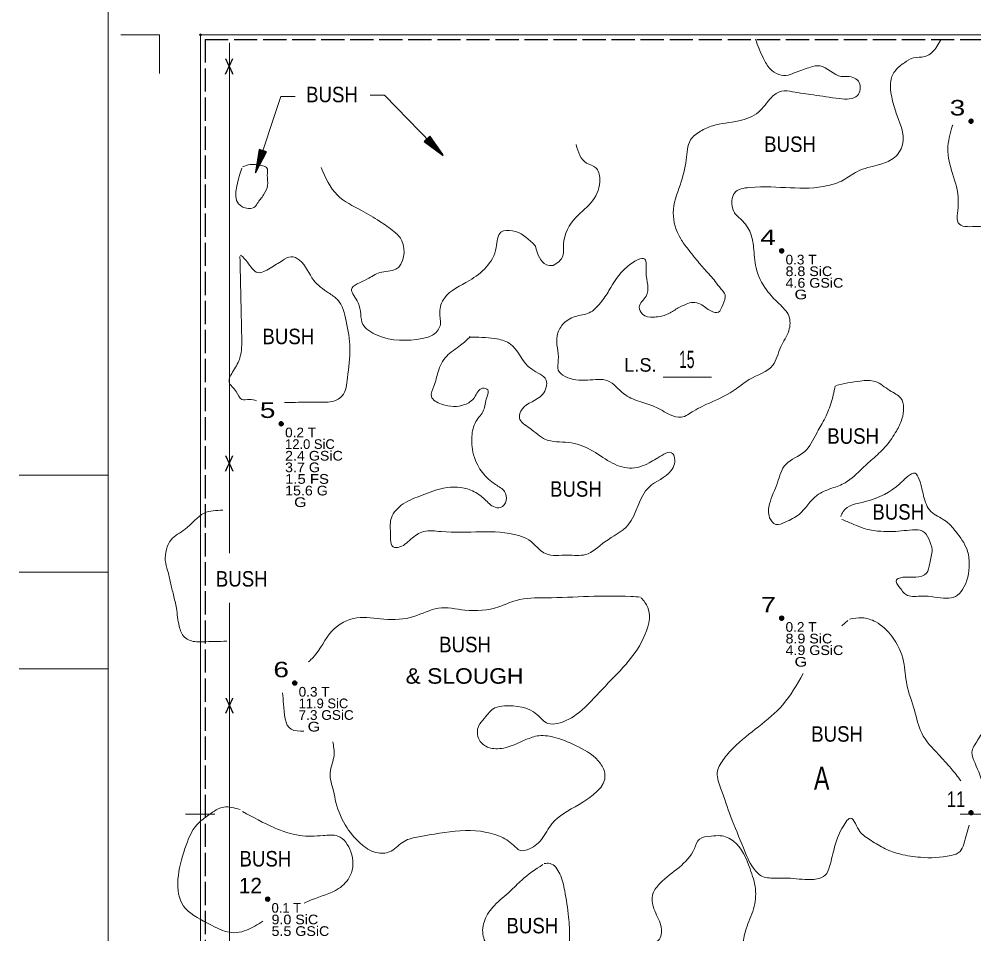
# Model space of a CAD drawing. Extents: x -496 to 480, y -452 to 700.
# Drawn here: x -496.1 to -2.8, y -61.9 to 410.5 of the extents above; entities that cross this region are included whole.
import ezdxf
from ezdxf.enums import TextEntityAlignment as Align

# ---------------------------------------------------------------- set-up
doc = ezdxf.new("R2010")
doc.units = 0
doc.header["$LTSCALE"] = 2
doc.header["$PDMODE"] = 32
doc.header["$PDSIZE"] = 1
doc.linetypes.add('LONG_DASHED', pattern=[7.5, 6, -1.5])
doc.layers.add('3', color=7, linetype='Continuous', lineweight=13)

msp = doc.modelspace()

# ---------------------------------------------------------------- linework, layer by layer
at = {"layer": '3'}
for p, q in [((-423.537, 402.339), (-443.537, 402.339)), ((-423.537, 402.339), (-423.537, 382.339)), ((-402.391, 402.339), (-402.391, -402.333)), ((-382.391, 402.339), (-402.391, 402.339)), ((-387.448, 398.168), (-387.448, 134.718)), ((-230.688, 294.819), (-229.391, 293.153)), ((-220.248, 283.152), (-217.731, 284.727)), ((-163.382, 225.602), (-138.382, 225.602)), ((-450.017, 174.973), (-496.057, 174.973)), ((-450.017, 124.973), (-496.057, 124.973)), ((-387.448, 109.099), (-387.448, -402.333)), ((-71.129, 97.14), (-68.036, 99.92)), ((-450.017, 74.973), (-496.057, 74.973)), ((-395.017, -0.027), (-410.017, -0.027)), ((-10.017, -0.027), (9.983, -0.027))]:
    msp.add_line(p, q, dxfattribs=at)
at = {"layer": '3', "linetype": 'LONG_DASHED', "lineweight": 25}
for q in [(292.281, 400), (-400, -400)]:
    msp.add_line((-400, 400), q, dxfattribs=at)
at = {"layer": '3'}
for points in [[(449.983, -450.027), (449.983, 399.973), (449.983, 699.973), (-450.017, 699.973), (-450.017, 49.973), (-450.017, -450.027)], [(402.281, -402.333), (402.281, 402.339), (-402.391, 402.339)], [(-353.522, 370.559), (-360.926, 370.559), (-373.884, 331.114)], [(-314.648, 371.175), (-307.243, 371.175), (-277.008, 340.05)]]:
    msp.add_lwpolyline(points, dxfattribs=at)
at = {"layer": '3', "lineweight": 25}
for points in [[(-277.008, 340.05), (-283.935, 350.051), (-286.804, 347.264)], [(-373.884, 331.114), (-368.239, 341.89), (-372.039, 343.138)]]:
    msp.add_lwpolyline(points, close=True, dxfattribs=at)
for points in [[(-283.951, 349.899), (-277.407, 340.463), (-286.573, 347.262), (-284.045, 349.746), (-277.92, 340.991), (-286.314, 347.242), (-284.034, 349.518), (-278.463, 341.549), (-286.023, 347.254), (-284.098, 349.275), (-279.064, 342.198), (-285.717, 347.218), (-284.103, 348.967), (-279.787, 342.975), (-285.395, 347.259), (-284.139, 348.632), (-280.569, 343.81), (-284.967, 347.285), (-284.127, 348.281), (-281.397, 344.756), (-284.541, 347.218), (-284.087, 347.868), (-282.452, 345.812), (-284.007, 347.194)], [(-368.382, 341.834), (-373.704, 331.658), (-371.934, 342.932), (-368.561, 341.846), (-373.474, 332.358), (-371.832, 342.694), (-368.757, 341.731), (-373.231, 333.098), (-371.685, 342.441), (-369.002, 341.674), (-372.936, 333.932), (-371.575, 342.154), (-369.277, 341.536), (-372.582, 334.932), (-371.389, 341.888), (-369.591, 341.412), (-372.205, 336.013), (-371.169, 341.521), (-369.896, 341.239), (-371.752, 337.185), (-371.03, 341.112), (-370.244, 341.012), (-371.306, 338.609), (-370.804, 340.628)]]:
    msp.add_lwpolyline(points, dxfattribs=at)
at = {"layer": '3', "lineweight": 35}
for centre in [(-4.317, 357.711), (-102.135, 290.769), (-360.654, 201.513), (-102.135, 101.1), (-353.667, 67.629), (-4.317, 0.687), (-367.641, -43.941)]:
    msp.add_circle(centre, 1, dxfattribs=at)
at = {"layer": '3'}
for points in [[(-115.696, 400.023), (-111.547, 390.14), (-108.036, 384.72), (-103.567, 381.851), (-98.78, 381.532), (-94.63, 383.126), (-90.8, 384.401), (-87.289, 385.676), (-82.501, 386.314), (-71.33, 380.894), (-68.138, 380.894), (-62.074, 377.706), (-63.032, 371.011), (-72.288, 369.417), (-85.693, 371.33), (-96.545, 372.924), (-102.291, 373.243), (-107.397, 370.055), (-114.1, 362.403), (-124.314, 357.94), (-137.719, 355.389), (-144.103, 352.52), (-149.21, 348.057), (-151.444, 337.855), (-154.636, 324.784), (-158.147, 310.437), (-154.317, 297.047), (-150.486, 291.628), (-146.656, 286.846), (-141.869, 281.107), (-136.443, 275.05), (-133.57, 271.224), (-131.336, 268.036), (-132.612, 262.935), (-134.847, 259.109), (-138.677, 259.747), (-144.103, 263.254), (-147.933, 264.21), (-151.444, 263.254), (-155.593, 261.341), (-160.381, 258.472), (-165.488, 256.878), (-168.36, 256.559), (-174.106, 258.153), (-175.702, 261.66), (-172.191, 267.398), (-172.191, 279.832), (-172.829, 286.527), (-181.766, 282.701), (-191.341, 270.268), (-195.81, 263.891), (-201.555, 258.79), (-208.896, 256.878), (-215.28, 252.733), (-218.152, 246.995), (-217.514, 234.242), (-217.514, 229.141), (-214.003, 225.953), (-202.513, 224.04), (-191.98, 223.721), (-183.681, 217.027), (-176.021, 213.201), (-167.722, 210.332), (-159.743, 206.187), (-153.997, 204.912), (-147.614, 208.1), (-138.677, 212.563), (-125.591, 219.577), (-118.888, 224.359), (-106.759, 231.692), (-102.61, 241.256), (-98.46, 249.545), (-98.46, 257.196), (-103.567, 263.573), (-109.951, 270.586), (-115.377, 282.063), (-116.654, 292.584), (-118.249, 299.917), (-123.037, 306.931), (-126.867, 311.075), (-127.825, 316.814), (-126.548, 320.639), (-118.569, 323.509), (-78.352, 324.465), (-70.373, 327.334), (-63.032, 331.798), (-51.86, 335.305), (-44.519, 338.493), (-39.732, 345.506), (-43.562, 363.679), (-45.796, 372.605)], [(-45.796, 372.605), (-45.796, 378.663), (-43.243, 384.082), (-38.774, 387.908), (-33.986, 390.458), (-28.241, 391.096), (-24.411, 393.328), (-19.942, 399.704)], [(301.264, 311.258), (296.565, 300.963), (289.413, 288.462), (287.029, 281.319), (281.07, 278.343), (257.232, 280.129), (241.737, 276.557), (236.97, 271.795), (230.414, 264.057), (224.455, 259.294), (214.919, 256.913), (204.192, 256.318), (197.041, 259.89), (182.142, 268.223), (175.587, 274.771), (171.415, 281.319), (167.243, 284.891), (157.708, 283.105), (149.365, 281.319), (133.87, 274.771), (125.527, 265.842), (116.588, 259.294), (109.436, 257.509), (99.305, 260.485), (93.942, 263.461), (84.406, 265.842), (74.871, 266.438), (70.104, 261.676), (64.74, 246.794), (64.144, 227.15), (62.356, 223.579), (55.205, 225.365), (53.417, 229.531), (51.629, 234.889), (45.074, 240.841), (26.599, 245.604), (21.832, 253.937), (18.852, 268.819), (14.68, 283.7), (14.084, 292.034), (14.084, 302.153), (14.68, 306.32), (9.913, 304.534), (-0.814, 303.344), (-10.35, 304.534), (-10.946, 314.654), (-16.309, 342.036), (-14.521, 353.346), (-13.809, 355.669)], [(-217.731, 284.727), (-215.511, 287.402), (-214.829, 294.212), (-208.352, 308.172), (-199.83, 316.684), (-196.081, 327.92), (-198.126, 333.708), (-202.898, 336.091), (-208.352, 345.625)], [(-380.709, 334.153), (-376.708, 335.369), (-370.969, 334.848), (-368.186, 333.805), (-367.838, 329.81), (-367.664, 324.598), (-369.751, 319.733), (-373.056, 315.216), (-374.795, 313.132), (-378.621, 312.784), (-381.056, 313.653), (-381.056, 333.458)], [(-340.009, 333.805), (-331.661, 319.56), (-319.138, 311.568), (-309.746, 306.009), (-302.441, 300.797), (-298.266, 295.933), (-301.397, 281.34), (-309.746, 279.603), (-316.355, 276.128), (-324.356, 270.916), (-320.877, 263.967), (-318.442, 252.849), (-311.137, 247.289), (-287.831, 245.552), (-281.917, 247.637), (-278.438, 252.849), (-278.786, 259.103), (-276.351, 266.399), (-263.481, 275.433), (-254.784, 282.382), (-249.566, 292.458), (-247.131, 300.45), (-241.218, 301.145), (-230.688, 294.819)], [(-229.391, 293.153), (-223.692, 283.657), (-220.248, 283.152)], [(-373.412, 213.433), (-377.066, 214.124), (-381.084, 214.124), (-383.88, 218.138), (-387.55, 223.025), (-385.278, 228.959), (-381.958, 235.591), (-381.084, 246.412), (-381.958, 287.951)], [(-381.609, 288.649), (-378.114, 284.983), (-372.872, 279.573), (-366.407, 281.842), (-359.942, 285.856), (-355.573, 287.776), (-351.205, 286.031), (-343.866, 275.559), (-336.178, 269.101), (-331.635, 265.611), (-327.092, 254.441), (-325.17, 240.478), (-326.393, 225.294), (-329.189, 215.869), (-333.557, 213.251), (-341.07, 212.728), (-353.302, 212.553), (-358.89, 212.514)], [(-263.515, 246.274), (-250.287, 245.481), (-242.879, 243.103), (-231.238, 229.625), (-223.83, 224.076), (-225.682, 216.677), (-236.265, 209.013), (-237.588, 204.521), (-232.296, 199.235), (-224.095, 193.422), (-212.189, 191.836), (-200.813, 188.136), (-190.759, 181.794), (-180.706, 178.623), (-170.652, 181.266), (-162.98, 185.758), (-159.011, 186.551), (-157.689, 184.701), (-159.276, 177.302), (-170.652, 168.845), (-181.5, 149.29), (-193.405, 140.569), (-203.459, 133.963), (-212.718, 133.699), (-224.095, 134.491), (-227.27, 136.606), (-232.826, 141.627), (-237.852, 143.741), (-278.067, 145.855), (-287.062, 145.855), (-293.676, 141.891), (-300.29, 137.663), (-302.142, 137.663), (-304.259, 145.326), (-303.73, 152.99), (-297.644, 160.125), (-287.856, 164.617), (-276.744, 168.317), (-262.722, 167.26), (-256.107, 163.032), (-251.081, 158.803), (-247.377, 158.275), (-244.467, 161.975), (-245.26, 166.467), (-250.022, 170.167), (-260.87, 184.172), (-262.193, 195.007), (-260.076, 202.671), (-256.107, 208.484), (-254.52, 215.091), (-253.991, 219.055), (-256.637, 219.848), (-260.87, 215.091), (-265.896, 211.391), (-277.802, 211.656), (-283.093, 215.619), (-281.77, 220.905), (-279.654, 228.304), (-275.156, 236.496), (-268.013, 242.046), (-262.986, 246.538)], [(-74.176, 221.296), (-61.538, 223.591), (-53.784, 223.304), (-46.316, 218.714), (-40.572, 214.698), (-39.998, 204.083), (-42.87, 197.772), (-48.04, 190.313), (-54.358, 184.002), (-60.39, 178.551), (-69.293, 171.093), (-76.186, 168.224), (-83.941, 164.494), (-93.132, 154.74), (-100.312, 150.724), (-105.194, 149.577), (-108.354, 153.019), (-108.354, 160.191), (-104.333, 171.093), (-100.025, 180.559), (-90.259, 187.158), (-84.228, 196.338), (-80.207, 203.51), (-76.761, 211.829), (-74.463, 221.009)], [(-71.591, 153.593), (-70.442, 156.175), (-58.954, 161.339), (-41.146, 170.519), (-37.126, 174.248), (-33.105, 175.969), (-31.669, 173.961), (-28.796, 164.207), (-25.063, 156.175), (-17.882, 151.585), (-12.138, 145.847), (-6.394, 136.38), (-5.245, 129.208), (-8.692, 116.012), (-12.425, 112.283), (-17.021, 111.422), (-29.658, 112.569), (-37.126, 112.856), (-41.146, 116.873), (-42.87, 120.889), (-40.572, 122.036), (-32.817, 122.323), (-27.36, 124.331), (-25.637, 129.495), (-24.488, 136.38), (-26.212, 142.118), (-29.371, 146.134), (-34.541, 146.708), (-46.029, 145.847), (-52.635, 146.134), (-56.656, 146.708), (-65.559, 149.864), (-71.016, 152.159)], [(-390.859, 156.886), (-400.449, 155.389), (-410.339, 147.007), (-417.532, 141.619), (-419.93, 136.53), (-420.529, 130.842), (-419.331, 125.753), (-417.832, 119.466), (-416.333, 113.18), (-414.835, 106.294), (-413.336, 97.014), (-410.639, 91.327), (-404.345, 88.932), (-401.048, 88.932), (-388.761, 89.231)], [(-346.521, 78.576), (-344.081, 80.888), (-334.371, 94.6), (-321.647, 101.289), (-307.584, 100.62), (-292.182, 101.958), (-279.459, 106.305), (-265.73, 105.302), (-248.319, 106.974), (-239.279, 110.319), (-223.876, 111.657), (-180.013, 112.325), (-174.991, 111.991)], [(-174.656, 111.657), (-171.308, 106.64), (-173.651, 90.586), (-182.692, 77.209), (-194.746, 64.5), (-206.8, 52.46), (-218.184, 46.774), (-222.872, 46.774), (-228.564, 51.456), (-245.306, 55.804), (-250.328, 54.801), (-255.685, 49.45), (-258.699, 45.436), (-258.364, 38.413), (-255.685, 35.403), (-248.989, 33.731), (-240.283, 35.738), (-234.256, 38.413), (-227.559, 40.42), (-218.854, 39.416), (-207.135, 34.734), (-195.75, 26.039), (-193.407, 20.353), (-206.8, 4.969), (-220.863, -5.065), (-226.22, -13.091), (-233.586, -18.443), (-237.27, -18.777), (-240.618, -16.101), (-247.984, -11.419), (-289.503, -11.754), (-297.205, -14.095), (-303.901, -19.111), (-310.598, -20.115), (-318.634, -16.101), (-326.67, -7.071), (-332.362, 5.972), (-333.701, 11.992), (-335.376, 21.356), (-333.367, 30.386), (-334.056, 37.304)], [(-67.104, 100.619), (-60.576, 101.317), (-53.583, 99.222), (-45.19, 91.77), (-39.129, 78.731), (-37.497, 66.856), (-33.534, 53.583), (-29.805, 41.708), (-21.179, 30.764), (-14.652, 23.546), (-9.585, 17.207)], [(-5.288, -5.663), (-8.125, -15.573), (-9.99, -19.298), (-14.652, -21.394), (-30.504, -22.325), (-40.761, -20.695), (-48.687, -17.901), (-55.914, -13.71), (-61.742, -9.053), (-64.073, -4.862), (-66.637, -2.067), (-68.968, -4.163), (-74.796, -16.97), (-77.361, -26.982), (-79.692, -31.639), (-83.888, -33.502), (-96.243, -33.269), (-107.666, -33.036), (-111.163, -32.571), (-116.758, -27.914), (-121.886, -17.435), (-128.414, -1.369), (-133.542, 13.068), (-135.407, 21.217), (-132.377, 27.97), (-127.015, 34.257), (-101.605, 56.378), (-91.037, 72.499)], [(-348.914, 42.778), (-355.466, 43.764), (-359.484, 56.808), (-359.995, 62.519)], [(2.873, 9.804), (2.023, 14.186), (-2.274, 26.258), (-3.885, 31.891), (-0.931, 38.061), (0.949, 41.28)], [(-370.238, -55.37), (-378.569, -59.914), (-383.591, -61.251), (-398.994, -56.235), (-411.048, -47.539), (-410.378, -17.774), (-404.016, -5.399), (-397.989, -0.382), (-390.288, 3.631), (-381.917, 2.293)], [(-380.578, 1.29), (-364.171, -7.071), (-351.113, -11.085), (-339.059, -11.085), (-331.358, -11.419), (-324.661, -19.446), (-324.996, -31.82), (-331.023, -38.509), (-344.751, -44.195), (-348.873, -46.071)], [(-199.95, -106.612), (-199.61, -97.793), (-197.09, -89.738), (-191.294, -83.697), (-185.749, -77.403), (-179.701, -70.607), (-173.149, -67.586), (-168.36, -66.579), (-165.336, -64.566), (-164.58, -57.517), (-168.108, -48.959), (-168.612, -41.155), (-165.084, -35.869), (-147.191, -17.745), (-144.671, -12.962), (-138.623, -11.452), (-133.834, -11.2), (-127.03, -13.969), (-118.461, -28.318), (-115.689, -38.638), (-116.697, -48.959), (-120.477, -59.279), (-122.242, -67.083), (-123.502, -76.9), (-122.242, -87.472), (-117.705, -97.29), (-111.718, -107.854)], [(-224.812, -25.549), (-221.787, -25.549), (-216.747, -30.835), (-214.227, -39.645), (-212.211, -53.238), (-211.707, -63.559), (-212.715, -72.117), (-214.983, -77.152), (-220.275, -78.662), (-226.828, -79.166), (-235.144, -78.159), (-247.241, -72.872), (-252.533, -69.6), (-256.313, -63.055), (-255.557, -54.748), (-250.517, -47.197), (-242.453, -39.897), (-236.404, -34.107), (-225.568, -26.052)]]:
    msp.add_spline(points, degree=3, dxfattribs=at)
at = {"layer": '3', "lineweight": 35}
for points in [[(-4.328, 358.598), (-3.598, 358.194), (-3.446, 357.345), (-4.131, 356.817), (-4.94, 357.048), (-5.227, 357.806), (-4.98, 358.368), (-4.407, 358.536), (-3.733, 358.042), (-3.749, 357.3), (-4.266, 357.042), (-4.789, 357.211), (-5.013, 357.857), (-4.429, 358.323), (-3.991, 357.789), (-4.03, 357.306), (-4.659, 357.441), (-4.513, 358.076), (-4.221, 357.525)], [(-102.146, 291.656), (-101.416, 291.252), (-101.264, 290.403), (-101.949, 289.875), (-102.758, 290.106), (-103.045, 290.864), (-102.798, 291.426), (-102.225, 291.594), (-101.551, 291.1), (-101.567, 290.358), (-102.084, 290.1), (-102.607, 290.269), (-102.831, 290.915), (-102.247, 291.381), (-101.809, 290.847), (-101.848, 290.364), (-102.477, 290.499), (-102.331, 291.134), (-102.039, 290.583)], [(-360.665, 202.4), (-359.935, 201.996), (-359.783, 201.147), (-360.468, 200.619), (-361.277, 200.85), (-361.564, 201.608), (-361.317, 202.17), (-360.744, 202.338), (-360.07, 201.844), (-360.086, 201.102), (-360.603, 200.844), (-361.126, 201.013), (-361.35, 201.659), (-360.766, 202.125), (-360.328, 201.591), (-360.367, 201.108), (-360.996, 201.243), (-360.85, 201.878), (-360.558, 201.327)], [(-102.146, 101.987), (-101.416, 101.583), (-101.264, 100.734), (-101.949, 100.206), (-102.758, 100.437), (-103.045, 101.195), (-102.798, 101.757), (-102.225, 101.925), (-101.551, 101.431), (-101.567, 100.689), (-102.084, 100.431), (-102.607, 100.6), (-102.831, 101.246), (-102.247, 101.712), (-101.809, 101.178), (-101.848, 100.695), (-102.477, 100.83), (-102.331, 101.465), (-102.039, 100.914)], [(-353.678, 68.516), (-352.948, 68.112), (-352.796, 67.263), (-353.481, 66.735), (-354.29, 66.966), (-354.577, 67.724), (-354.33, 68.286), (-353.757, 68.454), (-353.083, 67.96), (-353.099, 67.218), (-353.616, 66.96), (-354.139, 67.129), (-354.363, 67.775), (-353.779, 68.241), (-353.341, 67.707), (-353.38, 67.224), (-354.009, 67.359), (-353.863, 67.994), (-353.571, 67.443)], [(-4.328, 1.574), (-3.598, 1.17), (-3.446, 0.321), (-4.131, -0.207), (-4.94, 0.024), (-5.227, 0.782), (-4.98, 1.344), (-4.407, 1.512), (-3.733, 1.018), (-3.749, 0.276), (-4.266, 0.018), (-4.789, 0.187), (-5.013, 0.833), (-4.429, 1.299), (-3.991, 0.765), (-4.03, 0.282), (-4.659, 0.417), (-4.513, 1.052), (-4.221, 0.501)], [(-367.652, -43.054), (-366.922, -43.458), (-366.77, -44.307), (-367.455, -44.835), (-368.264, -44.604), (-368.551, -43.846), (-368.304, -43.284), (-367.731, -43.116), (-367.057, -43.61), (-367.073, -44.352), (-367.59, -44.61), (-368.113, -44.441), (-368.337, -43.795), (-367.753, -43.329), (-367.315, -43.863), (-367.354, -44.346), (-367.983, -44.211), (-367.837, -43.576), (-367.545, -44.127)]]:
    msp.add_spline(points, degree=3, dxfattribs=at)
at = {"layer": '3'}
msp.add_point((-402.391, 402.339), dxfattribs=at)

# ---------------------------------------------------------------- texts
for s, height, width, p in [('X', 8, 0.7, (-387.565, 381.973)), ('BUSH', 8, 0.9, (-334.44, 367.516)), ('BUSH', 8, 0.9, (-97.819, 341.867)), ('BUSH', 8, 0.9, (-356.987, 242.602)), ('15', 8.89, 0.6, (-151.143, 230.298)), ('BUSH', 8, 0.9, (-65.232, 191.176)), ('X', 8, 0.7, (-387.529, 176.976)), ('BUSH', 8, 0.9, (-208.438, 163.854)), ('BUSH', 8, 0.9, (-41.941, 151.994)), ('BUSH', 8, 0.9, (-381.054, 117.435)), ('BUSH', 8, 0.9, (-265.686, 83.53)), ('& SLOUGH', 8, 1.1, (-265.971, 67.29)), ('X', 8, 0.7, (-387.432, 51.987)), ('BUSH', 8, 0.9, (-73.509, 37.346)), ('A', 12, 0.75, (-81.468, 12.524)), ('BUSH', 8, 0.9, (-368.835, -27.091)), ('BUSH', 8, 0.9, (-230.945, -61.606))]:
    msp.add_text(s, height=height, dxfattribs=dict(at, width=width)).set_placement(p, align=Align.CENTER)
for s, width, p in [('  3', 1.35, (-7.318, 360.711)), ('  4', 1.35, (-105.136, 293.769)), ('  5', 1.35, (-363.655, 204.513)), ('  7', 1.3, (-105.136, 104.1)), ('  6', 1.35, (-356.668, 70.629)), (' 11', 0.8, (-7.318, 3.687))]:
    msp.add_text(s, height=8, dxfattribs=dict(at, width=width)).set_placement(p, align=Align.RIGHT)
for s, width, p in [('0.3 T      ', 1.05, (-100.135, 283.769)), ('8.8 SiC    ', 1.1, (-100.135, 277.769)), ('4.6 GSiC   ', 1.1, (-100.135, 271.769)), ('  G        ', 1.25, (-100.135, 265.769)), ('0.2 T      ', 1.05, (-358.654, 194.513)), ('2.4 GSiC   ', 1.1, (-358.654, 182.513)), ('3.7 G      ', 1.1, (-358.654, 176.513)), ('1.5 FS     ', 1.15, (-358.654, 170.513)), ('15.6 G     ', 1.1, (-358.654, 164.513)), ('  G        ', 1.25, (-358.654, 158.513)), ('0.2 T      ', 1.05, (-100.135, 94.1)), ('8.9 SiC    ', 1.1, (-100.135, 88.1)), ('4.9 GSiC   ', 1.1, (-100.135, 82.1)), ('  G        ', 1.25, (-100.135, 76.1)), ('0.3 T      ', 1.05, (-351.667, 60.629)), ('7.3 GSiC   ', 1.05, (-351.667, 48.629)), ('  G        ', 1.25, (-351.667, 42.629)), ('9.0 SiC    ', 1.1, (-365.641, -56.941)), ('5.5 GSiC   ', 1.1, (-365.641, -62.941))]:
    msp.add_text(s, height=5, dxfattribs=dict(at, width=width)).set_placement(p)
msp.add_text('L.S.', height=7, dxfattribs=at).set_placement((-175.104, 228.395), align=Align.CENTER)
for s, p in [('12.0 SiC   ', (-358.654, 188.513)), ('11.9 SiC   ', (-351.667, 54.629)), ('0.1 T      ', (-365.641, -50.941))]:
    msp.add_text(s, height=5, dxfattribs=at).set_placement(p)
msp.add_text(' 12', height=8, dxfattribs=at).set_placement((-370.642, -40.941), align=Align.RIGHT)

doc.saveas('drawing.dxf')
